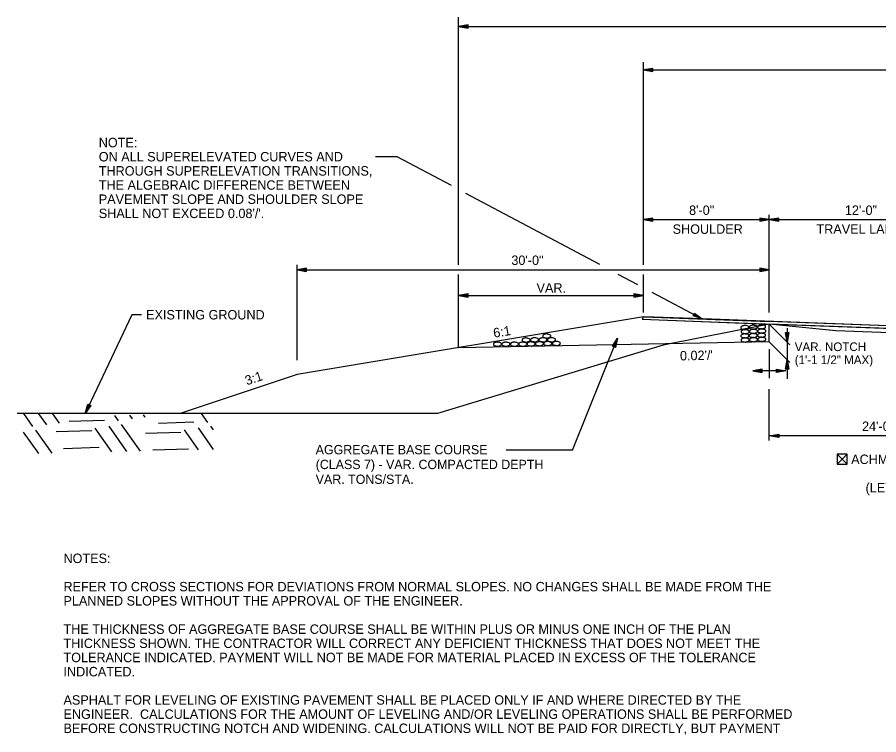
# Model space of a CAD drawing. Extents: x 1461846 to 1462006, y 1686171 to 1686805.
# Drawn here: x 1461847.7 to 1461902.5, y 1686488 to 1686533.5 of the extents above; entities that cross this region are included whole.
import ezdxf

# ---------------------------------------------------------------- set-up
doc = ezdxf.new("R2010")
doc.units = 0
for name, color, linetype in [('1', 7, 'Continuous'), ('10', 7, 'Continuous'), ('19', 7, 'Continuous'), ('20', 7, 'Continuous'), ('R_Draft', 7, 'Continuous')]:
    doc.layers.add(name, color=color, linetype=linetype)

# ---------------------------------------------------------------- blocks, each defined once
blk = doc.blocks.new('ROCKS')
at = {"layer": '1'}
blk.add_spline([(0.013, 0.06), (0.053, 0.053), (0.107, 0.033), (0.133, 0.013), (0.133, -0.007), (0.12, -0.033), (0.107, -0.04), (0.073, -0.053), (0.033, -0.067), (0.013, -0.067), (-0.02, -0.06), (-0.06, -0.053), (-0.087, -0.047), (-0.113, -0.02), (-0.113, -0.007), (-0.107, 0.02), (-0.087, 0.033), (-0.067, 0.047), (-0.033, 0.053), (-0.02, 0.06), (0.013, 0.06)], degree=3, dxfattribs=at)

msp = doc.modelspace()

# ---------------------------------------------------------------- linework, layer by layer
at = {"layer": '10'}
for p, q in [((1461899.829, 1686505.785), (1461900.47, 1686505.143)), ((1461900.47, 1686505.785), (1461899.829, 1686505.143))]:
    msp.add_line(p, q, dxfattribs=at)
msp.add_lwpolyline([(1461900.221, 1686505.143), (1461900.47, 1686505.143), (1461900.47, 1686505.785), (1461899.829, 1686505.785), (1461899.829, 1686505.143), (1461900.21, 1686505.143)], dxfattribs=at)
at = {"layer": '19'}
for p, q in [((1461887.514, 1686514.515), (1461887.432, 1686514.352)), ((1461896.545, 1686513.511), (1461896.755, 1686513.511)), ((1461896.65, 1686512.911), (1461896.545, 1686513.511)), ((1461896.635, 1686513.071), (1461896.595, 1686513.511)), ((1461896.755, 1686513.511), (1461896.65, 1686512.911)), ((1461896.7, 1686513.511), (1461896.665, 1686513.071)), ((1461883.01, 1686506.041), (1461885.863, 1686513.161)), ((1461885.543, 1686512.644), (1461885.863, 1686513.161)), ((1461885.589, 1686512.626), (1461885.788, 1686513.019)), ((1461885.815, 1686513.009), (1461885.688, 1686512.588)), ((1461885.863, 1686513.161), (1461885.736, 1686512.565)), ((1461885.736, 1686512.565), (1461885.543, 1686512.644)), ((1461896.545, 1686511.186), (1461896.65, 1686511.786)), ((1461896.65, 1686511.786), (1461896.755, 1686511.186)), ((1461896.755, 1686511.186), (1461896.545, 1686511.186)), ((1461896.6, 1686511.186), (1461896.635, 1686511.626)), ((1461896.665, 1686511.626), (1461896.705, 1686511.186)), ((1461848.716, 1686507.537), (1461848.133, 1686508.371)), ((1461849.608, 1686507.651), (1461849.104, 1686508.357)), ((1461850.401, 1686507.762), (1461849.994, 1686508.344)), ((1461853.274, 1686507.917), (1461851.014, 1686507.851)), ((1461854.162, 1686507.91), (1461853.928, 1686508.243)), ((1461855.055, 1686508.023), (1461854.883, 1686508.264)), ((1461855.847, 1686508.135), (1461855.738, 1686508.282)), ((1461859.842, 1686507.797), (1461859.436, 1686508.371)), ((1461853.738, 1686505.94), (1461852.669, 1686507.447)), ((1461854.693, 1686505.961), (1461853.562, 1686507.561)), ((1461855.548, 1686505.979), (1461854.354, 1686507.672)), ((1461858.953, 1686507.815), (1461856.694, 1686507.739)), ((1461859.246, 1686506.068), (1461858.349, 1686507.335)), ((1461860.201, 1686506.089), (1461859.241, 1686507.449)), ((1461860.193, 1686507.338), (1461860.034, 1686507.56)), ((1461849.085, 1686505.83), (1461848.115, 1686507.188)), ((1461849.939, 1686505.849), (1461848.907, 1686507.3)), ((1461852.46, 1686507.269), (1461850.19, 1686507.201)), ((1461858.128, 1686507.165), (1461855.87, 1686507.089)), ((1461852.927, 1686506.21), (1461850.669, 1686506.133)), ((1461858.607, 1686506.097), (1461856.338, 1686506.03)), ((1461883.01, 1686506.041), (1461878.8, 1686506.041))]:
    msp.add_line(p, q, dxfattribs=at)
msp.add_lwpolyline([(1461887.432, 1686514.352), (1461891.238, 1686514.211), (1461911.417, 1686513.464), (1461930.555, 1686512.756), (1461938.176, 1686512.474), (1461948.934, 1686512.076), (1461954.677, 1686511.863), (1461956.599, 1686511.786), (1461962.599, 1686511.546), (1461962.599, 1686511.546), (1461962.599, 1686511.546), (1461962.514, 1686511.716), (1461962.514, 1686511.716), (1461962.514, 1686511.716), (1461956.649, 1686511.951), (1461948.529, 1686512.258), (1461938.2, 1686512.64), (1461930.551, 1686512.923), (1461911.463, 1686513.629), (1461891.292, 1686514.375), (1461887.514, 1686514.515)], close=True, dxfattribs=at)
at = {"layer": '20'}
for p, q in [((1461875.769, 1686529.153), (1461875.769, 1686533.547)), ((1461876.369, 1686533.07), (1461875.769, 1686532.965)), ((1461876.369, 1686532.86), (1461876.369, 1686533.07)), ((1461875.769, 1686532.965), (1461972.291, 1686532.965)), ((1461875.769, 1686532.965), (1461876.369, 1686532.86)), ((1461876.369, 1686533.015), (1461875.929, 1686532.98)), ((1461875.929, 1686532.95), (1461876.369, 1686532.91)), ((1461887.514, 1686520.985), (1461887.514, 1686530.686)), ((1461888.114, 1686530.3), (1461887.514, 1686530.195)), ((1461887.514, 1686530.195), (1461962.514, 1686530.195)), ((1461887.514, 1686530.195), (1461888.114, 1686530.09)), ((1461888.114, 1686530.245), (1461887.674, 1686530.21)), ((1461887.674, 1686530.18), (1461888.114, 1686530.14)), ((1461888.114, 1686530.09), (1461888.114, 1686530.3)), ((1461875.769, 1686517.806), (1461875.769, 1686529.153)), ((1461875.769, 1686512.533), (1461875.769, 1686517.206)), ((1461876.369, 1686515.97), (1461875.769, 1686515.865)), ((1461875.769, 1686515.865), (1461887.514, 1686515.865)), ((1461875.769, 1686515.865), (1461876.369, 1686515.76)), ((1461876.369, 1686515.915), (1461875.929, 1686515.88)), ((1461875.929, 1686515.85), (1461876.369, 1686515.81)), ((1461876.369, 1686515.76), (1461876.369, 1686515.97)), ((1461886.914, 1686515.97), (1461886.914, 1686515.76)), ((1461887.514, 1686515.865), (1461886.914, 1686515.97)), ((1461887.354, 1686515.88), (1461886.914, 1686515.915)), ((1461886.914, 1686515.76), (1461887.514, 1686515.865)), ((1461886.914, 1686515.81), (1461887.354, 1686515.85)), ((1461895.514, 1686514.053), (1461896.827, 1686512.738)), ((1461895.514, 1686512.928), (1461896.827, 1686511.613))]:
    msp.add_line(p, q, dxfattribs=at)
msp.add_lwpolyline([(1461896.65, 1686513.788), (1461896.65, 1686510.578)], dxfattribs=at)
at = {"layer": 'R_Draft'}
for p, q in [((1461887.514, 1686517.806), (1461887.514, 1686520.985)), ((1461888.114, 1686520.79), (1461887.514, 1686520.685)), ((1461887.514, 1686520.685), (1461895.514, 1686520.685)), ((1461887.514, 1686520.685), (1461888.114, 1686520.58)), ((1461888.114, 1686520.735), (1461887.674, 1686520.7)), ((1461887.674, 1686520.67), (1461888.114, 1686520.63)), ((1461888.114, 1686520.58), (1461888.114, 1686520.79)), ((1461894.914, 1686520.79), (1461894.914, 1686520.58)), ((1461895.514, 1686520.685), (1461894.914, 1686520.79)), ((1461895.354, 1686520.7), (1461894.914, 1686520.735)), ((1461894.914, 1686520.58), (1461895.514, 1686520.685)), ((1461894.914, 1686520.63), (1461895.354, 1686520.67)), ((1461895.514, 1686514.787), (1461895.514, 1686520.985)), ((1461896.114, 1686520.79), (1461895.514, 1686520.685)), ((1461895.514, 1686520.685), (1461907.514, 1686520.685)), ((1461895.514, 1686520.685), (1461896.114, 1686520.58)), ((1461896.114, 1686520.735), (1461895.674, 1686520.7)), ((1461895.674, 1686520.67), (1461896.114, 1686520.63)), ((1461896.114, 1686520.58), (1461896.114, 1686520.79)), ((1461865.514, 1686511.763), (1461865.514, 1686517.806)), ((1461866.114, 1686517.611), (1461865.514, 1686517.506)), ((1461865.514, 1686517.506), (1461895.514, 1686517.506)), ((1461865.514, 1686517.506), (1461866.114, 1686517.401)), ((1461866.114, 1686517.556), (1461865.674, 1686517.521)), ((1461865.674, 1686517.491), (1461866.114, 1686517.451)), ((1461866.114, 1686517.401), (1461866.114, 1686517.611)), ((1461887.514, 1686514.787), (1461887.514, 1686517.206)), ((1461894.914, 1686517.611), (1461894.914, 1686517.401)), ((1461895.514, 1686517.506), (1461894.914, 1686517.611)), ((1461895.354, 1686517.521), (1461894.914, 1686517.556)), ((1461894.914, 1686517.401), (1461895.514, 1686517.506)), ((1461894.914, 1686517.451), (1461895.354, 1686517.491)), ((1461887.514, 1686514.515), (1461865.514, 1686510.849)), ((1461887.514, 1686514.515), (1461895.514, 1686514.219)), ((1461890.666, 1686514.566), (1461890.765, 1686514.752)), ((1461891.245, 1686514.377), (1461890.666, 1686514.566)), ((1461891.097, 1686514.439), (1461890.69, 1686514.611)), ((1461890.739, 1686514.703), (1461891.111, 1686514.466)), ((1461890.765, 1686514.752), (1461891.245, 1686514.377)), ((1461887.432, 1686514.352), (1461895.514, 1686514.053)), ((1461895.514, 1686512.928), (1461895.514, 1686514.053)), ((1461895.514, 1686512.928), (1461875.769, 1686512.533)), ((1461895.514, 1686512.455), (1461895.514, 1686510.619)), ((1461895.067, 1686511.176), (1461894.467, 1686511.071)), ((1461895.067, 1686510.966), (1461895.067, 1686511.176)), ((1461895.962, 1686510.966), (1461895.962, 1686511.176)), ((1461895.962, 1686511.176), (1461896.562, 1686511.071)), ((1461865.514, 1686510.849), (1461858.081, 1686508.371)), ((1461894.467, 1686511.071), (1461895.067, 1686510.966)), ((1461896.562, 1686511.071), (1461894.467, 1686511.071)), ((1461895.067, 1686511.121), (1461894.627, 1686511.086)), ((1461894.627, 1686511.056), (1461895.067, 1686511.016)), ((1461895.962, 1686511.121), (1461896.402, 1686511.086)), ((1461896.562, 1686511.071), (1461895.962, 1686510.966)), ((1461896.402, 1686511.056), (1461895.962, 1686511.016)), ((1461895.514, 1686506.659), (1461895.514, 1686509.918)), ((1461852.047, 1686508.371), (1461852.21, 1686508.958)), ((1461852.398, 1686508.868), (1461852.047, 1686508.371)), ((1461852.106, 1686508.518), (1461852.256, 1686508.93)), ((1461852.355, 1686508.884), (1461852.13, 1686508.51)), ((1461852.21, 1686508.958), (1461852.398, 1686508.868)), ((1461874.437, 1686508.371), (1461847.723, 1686508.371)), ((1461895.514, 1686506.959), (1461896.114, 1686507.064)), ((1461919.514, 1686506.959), (1461895.514, 1686506.959)), ((1461896.114, 1686506.854), (1461895.514, 1686506.959)), ((1461895.674, 1686506.974), (1461896.114, 1686507.009)), ((1461896.114, 1686506.904), (1461895.674, 1686506.944)), ((1461896.114, 1686507.064), (1461896.114, 1686506.854))]:
    msp.add_line(p, q, dxfattribs=at)
for points in [[(1461870.483, 1686524.701), (1461871.845, 1686524.701), (1461875.292, 1686522.867)], [(1461876.212, 1686522.377), (1461884.723, 1686517.848)], [(1461885.89, 1686517.227), (1461887.131, 1686516.566)], [(1461888.055, 1686516.075), (1461891.245, 1686514.377)], [(1461855.613, 1686514.643), (1461855.013, 1686514.643), (1461852.047, 1686508.371)], [(1462004.832, 1686512.162), (1461984.872, 1686511.458), (1461970.134, 1686507.926), (1461968, 1686507.772), (1461963.59, 1686507.904), (1461955.708, 1686508.135), (1461934.695, 1686508.743), (1461919.514, 1686513.165), (1461918.223, 1686513.06), (1461917.452, 1686512.972), (1461899.751, 1686513.614), (1461895.514, 1686514.053), (1461888.778, 1686512.7), (1461874.437, 1686508.371)], [(1461954.514, 1686512.036), (1461925.014, 1686513.128), (1461895.514, 1686514.219)], [(1461909.514, 1686513.535), (1461895.514, 1686514.053)], [(1461954.514, 1686511.87), (1461925.014, 1686512.961), (1461895.514, 1686514.053)]]:
    msp.add_lwpolyline(points, dxfattribs=at)

# ---------------------------------------------------------------- block references
at = {"layer": '19', "xscale": 2.0611362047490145, "yscale": 2.061136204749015, "rotation": 0.1831481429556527}
for p in [(1461893.945, 1686513.84), (1461894.474, 1686513.86), (1461895.003, 1686513.881), (1461893.945, 1686513.31), (1461893.963, 1686513.578), (1461894.474, 1686513.33), (1461894.492, 1686513.599), (1461895.003, 1686513.351), (1461895.021, 1686513.62), (1461893.963, 1686513.048), (1461894.492, 1686513.069), (1461895.021, 1686513.09)]:
    msp.add_blockref('ROCKS', p, dxfattribs=at)
at = {"layer": '19', "xscale": 2.061136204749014, "yscale": 2.061136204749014}
for p in [(1461881.347, 1686513.298), (1461878.217, 1686512.78), (1461878.756, 1686512.78), (1461879.3, 1686512.78), (1461879.827, 1686512.78), (1461880.034, 1686513.043), (1461880.358, 1686512.794), (1461880.577, 1686513.059), (1461880.882, 1686512.807), (1461881.11, 1686513.059), (1461881.415, 1686512.817), (1461881.652, 1686513.059), (1461881.96, 1686512.826)]:
    msp.add_blockref('ROCKS', p, dxfattribs=at)

# ---------------------------------------------------------------- texts
at = {"layer": '10'}
for s, p in [('VAR. NOTCH', (1461897.131, 1686512.334)), ('(1\'-1 1/2" MAX)', (1461897.131, 1686511.505))]:
    msp.add_text(s, height=0.55, dxfattribs=at).set_placement(p)
at = {"layer": '19'}
for s, p in [('AGGREGATE BASE COURSE', (1461866.689, 1686505.776)), ('(CLASS 7) - VAR. COMPACTED DEPTH', (1461866.689, 1686504.836)), ('VAR. TONS/STA.', (1461866.689, 1686503.896))]:
    msp.add_text(s, height=0.59001, rotation=360, dxfattribs=at).set_placement(p)
at = {"layer": 'R_Draft'}
for s, p in [('NOTE:', (1461852.905, 1686525.285)), ('ON ALL SUPERELEVATED CURVES AND', (1461852.905, 1686524.385)), ('THROUGH SUPERELEVATION TRANSITIONS,', (1461852.905, 1686523.485)), ('THE ALGEBRAIC DIFFERENCE BETWEEN', (1461852.905, 1686522.585)), ('PAVEMENT SLOPE AND SHOULDER SLOPE', (1461852.905, 1686521.685)), ('8\'-0"', (1461890.416, 1686520.985)), ('12\'-0"', (1461900.317, 1686520.985)), ("SHALL NOT EXCEED 0.08'/'.", (1461852.905, 1686520.785)), ('SHOULDER', (1461889.372, 1686519.785)), ('TRAVEL LANE', (1461898.514, 1686519.785)), ('30\'-0"', (1461879.123, 1686517.806)), ('EXISTING GROUND', (1461855.913, 1686514.344)), ('24\'-0" EXISTING PAVEMENT', (1461901.408, 1686507.259)), ('ACHM SURFACE COURSE (1/2")', (1461900.716, 1686505.159)), ('(LEVELING) & TACK COATS', (1461901.632, 1686503.359)), ('NOTES:', (1461850.662, 1686498.867)), ('REFER TO CROSS SECTIONS FOR DEVIATIONS FROM NORMAL SLOPES. NO CHANGES SHALL BE MADE FROM THE ', (1461850.662, 1686497.067)), ('PLANNED SLOPES WITHOUT THE APPROVAL OF THE ENGINEER.', (1461850.662, 1686496.167)), ('THE THICKNESS OF AGGREGATE BASE COURSE SHALL BE WITHIN PLUS OR MINUS ONE INCH OF THE PLAN ', (1461850.662, 1686494.367)), ('THICKNESS SHOWN. THE CONTRACTOR WILL CORRECT ANY DEFICIENT THICKNESS THAT DOES NOT MEET THE ', (1461850.662, 1686493.467)), ('TOLERANCE INDICATED. PAYMENT WILL NOT BE MADE FOR MATERIAL PLACED IN EXCESS OF THE TOLERANCE ', (1461850.662, 1686492.567)), ('INDICATED.', (1461850.662, 1686491.667)), ('ASPHALT FOR LEVELING OF EXISTING PAVEMENT SHALL BE PLACED ONLY IF AND WHERE DIRECTED BY THE ', (1461850.662, 1686489.867)), ('ENGINEER.  CALCULATIONS FOR THE AMOUNT OF LEVELING AND/OR LEVELING OPERATIONS SHALL BE PERFORMED ', (1461850.662, 1686488.967)), ('BEFORE CONSTRUCTING NOTCH AND WIDENING. CALCULATIONS WILL NOT BE PAID FOR DIRECTLY, BUT PAYMENT ', (1461850.662, 1686488.067))]:
    msp.add_text(s, height=0.6, dxfattribs=at).set_placement(p)
for s, rotation, p in [('VAR.', 360, (1461880.725, 1686516.048)), ('6:1', 9.4825, (1461878.025, 1686513.177)), ("0.02'/'", 1.1458, (1461889.843, 1686511.738)), ('3:1', 18.4349, (1461862.312, 1686510.153))]:
    msp.add_text(s, height=0.6, rotation=rotation, dxfattribs=at).set_placement(p)

doc.saveas('drawing.dxf')
